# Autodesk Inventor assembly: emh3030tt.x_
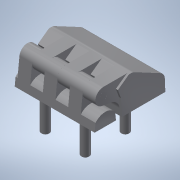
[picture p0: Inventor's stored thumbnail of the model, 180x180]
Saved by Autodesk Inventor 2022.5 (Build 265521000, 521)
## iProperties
Part Number: emh3030tt.x_
Material: 一般
Document SubType Name: Assembly
Designer: ImaoCorp
Sending System: SOLIDWORKS 2017-2017317
MC: AMD64
MC_MODEL: Intel64 Family 6 Model 60 Stepping 3, GenuineIntel
OS: Windows_NT
FRU: Parasolid Version 29.0, build 201,  4-17-2017
FORMAT: text
GUISE: transmit
KEY: emh3030tt
FILE: emh3030tt.x_t
DATE: Mon May 13 14:20:36 2019
Author: ImaoCorp
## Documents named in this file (4)
- X:\14_SW2022-Inv2022\00_全2023-1023新製品(TCC)まで\e\emh3030tt\EMH3030TT.iam
- X:\14_SW2022-Inv2022\00_全2023-1023新製品(TCC)まで\e\emh3030tt\emh3030tt_01.ipt
- X:\14_SW2022-Inv2022\00_全2023-1023新製品(TCC)まで\e\emh3030tt\emh3030tt_02.ipt
- X:\14_SW2022-Inv2022\00_全2023-1023新製品(TCC)まで\e\emh3030tt\emh3030tt_03.ipt
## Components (3 placed, 3 different names)
1. emh3030tt_01
2. emh3030tt_02
3. emh3030tt_03
